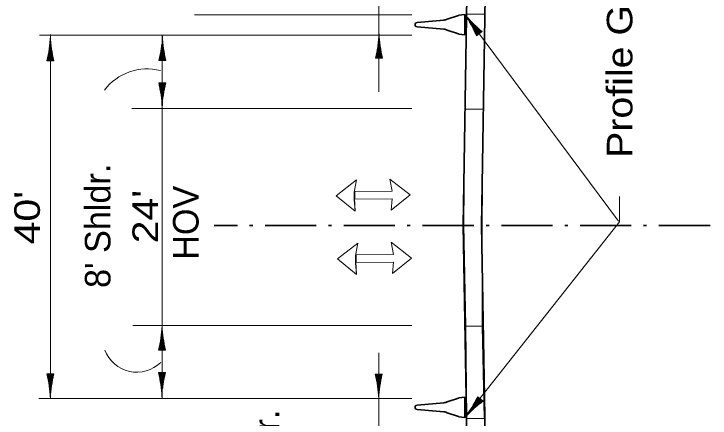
# Model space of a CAD drawing. Extents: x 2363427 to 2368559, y 6957299 to 6980140.
# Drawn here: x 2364817.6 to 2365198.6, y 6961278.3 to 6961499.8 of the extents above; entities that cross this region are included whole.
import ezdxf
from ezdxf.enums import TextEntityAlignment as Align

# ---------------------------------------------------------------- set-up
doc = ezdxf.new("R2010")
doc.units = 0
doc.header["$LTSCALE"] = 5.6
doc.linetypes.add('DOT_DASHED', pattern=[7.7, 5, -1.2, 0.3, -1.2])
for name, color, linetype, lineweight in [('3', 7, 'Continuous', 35), ('4', 7, 'Continuous', 13), ('40', 7, 'Continuous', 35), ('48', 7, 'Continuous', 25), ('8', 7, 'Continuous', 13)]:
    doc.layers.add(name, color=color, linetype=linetype, lineweight=lineweight)

msp = doc.modelspace()

# ---------------------------------------------------------------- linework, layer by layer
at = {"layer": '3'}
for p, q in [((2365063.563, 6961383.778), (2365066.183, 6961549.306)), ((2365073.563, 6961383.579), (2365076.183, 6961549.226)), ((2365054.789, 6961496.913), (2365060.903, 6961498.954)), ((2365061.067, 6961499.02), (2365061.077, 6961499.044)), ((2365064.339, 6961499.532), (2365061.077, 6961499.044)), ((2365064.339, 6961499.532), (2365061.273, 6961499.074)), ((2365064.339, 6961499.532), (2365064.339, 6961493.908)), ((2365037.269, 6961494.308), (2365037.269, 6961493.908)), ((2365053.001, 6961496.384), (2365038.297, 6961495.149)), ((2365037.269, 6961493.507), (2365037.269, 6961493.908)), ((2365053.001, 6961491.431), (2365038.297, 6961492.666)), ((2365054.789, 6961490.902), (2365060.903, 6961488.86)), ((2365064.339, 6961488.282), (2365064.339, 6961493.908)), ((2365061.067, 6961488.796), (2365061.077, 6961488.77)), ((2365064.339, 6961488.282), (2365061.077, 6961488.77)), ((2365064.339, 6961488.282), (2365061.273, 6961488.742)), ((2365063.563, 6961383.778), (2365066.169, 6961228.534)), ((2365073.563, 6961383.978), (2365076.177, 6961228.293)), ((2365054.789, 6961287.255), (2365060.903, 6961289.296)), ((2365061.067, 6961289.362), (2365061.077, 6961289.386)), ((2365064.339, 6961289.874), (2365061.077, 6961289.386)), ((2365064.339, 6961289.874), (2365061.273, 6961289.416)), ((2365064.339, 6961289.874), (2365064.339, 6961284.25)), ((2365053.001, 6961286.726), (2365038.297, 6961285.491)), ((2365037.269, 6961284.65), (2365037.269, 6961284.25)), ((2365037.269, 6961283.849), (2365037.269, 6961284.25)), ((2365053.001, 6961281.773), (2365038.297, 6961283.008)), ((2365054.789, 6961281.244), (2365060.903, 6961279.202)), ((2365064.339, 6961278.624), (2365064.339, 6961284.25)), ((2365061.067, 6961279.138), (2365061.077, 6961279.112)), ((2365064.339, 6961278.624), (2365061.077, 6961279.112)), ((2365064.339, 6961278.624), (2365061.273, 6961279.084))]:
    msp.add_line(p, q, dxfattribs=at)
at = {"layer": '3', "lineweight": 13}
for p, q in [((2365003.919, 6961397.784), (2365003.881, 6961401.879)), ((2365004.627, 6961363.108), (2365004.59, 6961367.202))]:
    msp.add_line(p, q, dxfattribs=at)
at = {"layer": '3', "linetype": 'DOT_DASHED'}
msp.add_line((2365198.639, 6961383.778), (2364927.223, 6961383.778), dxfattribs=at)
at = {"layer": '3', "lineweight": 13}
for points in [[(2365064.403, 6961447.572), (2365074.365, 6961447.572), (2365075.342, 6961499.674), (2365065.317, 6961499.575)], [(2365064.928, 6961328.633), (2365073.84, 6961328.633), (2365073.84, 6961384.173), (2365074.365, 6961447.572), (2365064.403, 6961447.572), (2365063.879, 6961384.173)], [(2365004.386, 6961391.664), (2364993.999, 6961400.199), (2365005.099, 6961408.802), (2365003.891, 6961402.074)], [(2365005.095, 6961356.988), (2364994.707, 6961365.522), (2365005.807, 6961374.125), (2365004.599, 6961367.398)], [(2365065.476, 6961278.05), (2365075.005, 6961278.05), (2365073.84, 6961328.633), (2365064.928, 6961328.633)]]:
    msp.add_lwpolyline(points, close=True, dxfattribs=at)
for points in [[(2365003.891, 6961402.074), (2365005.099, 6961408.802), (2364993.999, 6961400.199), (2365004.386, 6961391.664), (2364993.999, 6961400.199)], [(2364993.999, 6961400.199), (2365004.386, 6961391.664), (2365003.853, 6961397.979)], [(2365004.599, 6961367.398), (2365005.807, 6961374.125), (2364994.707, 6961365.522), (2365005.095, 6961356.988), (2364994.707, 6961365.522)], [(2364994.707, 6961365.522), (2365005.095, 6961356.988), (2365004.562, 6961363.302)]]:
    msp.add_lwpolyline(points, dxfattribs=at)
at = {"layer": '3'}
for centre, radius, start, end in [((2365061.451, 6961497.888), 1.2, 98.51269, 117.22516), ((2365038.416, 6961493.956), 1.2, 95.72178, 162.90786), ((2365052.5, 6961501.36), 5, 275.73538, 297.22872), ((2365038.416, 6961493.861), 1.2, 197.09214, 264.27822), ((2365052.5, 6961486.457), 5, 62.77128, 84.26462), ((2365061.451, 6961489.929), 1.2, 242.77484, 261.48731), ((2365061.451, 6961288.23), 1.2, 98.51269, 117.22516), ((2365038.417, 6961284.298), 1.2, 95.72178, 162.90786), ((2365052.501, 6961291.702), 5, 275.73538, 297.22872), ((2365038.417, 6961284.203), 1.2, 197.09214, 264.27822), ((2365052.501, 6961276.798), 5, 62.77128, 84.26462), ((2365061.451, 6961280.271), 1.2, 242.77484, 261.48731)]:
    msp.add_arc(centre, radius, start, end, dxfattribs=at)
at = {"layer": '4'}
for p, q in [((2365017.359, 6961457.18), (2365017.359, 6961524.971)), ((2365035.451, 6961499.296), (2364916.361, 6961499.296)), ((2365148.454, 6961386.156), (2365064.339, 6961499.532)), ((2365072.307, 6961488.867), (2365064.738, 6961498.896)), ((2365071.907, 6961488.568), (2365067.479, 6961494.433)), ((2365072.705, 6961489.169), (2365067.519, 6961496.04)), ((2365071.508, 6961488.265), (2365068.932, 6961491.679)), ((2365073.105, 6961489.47), (2365070.176, 6961493.351)), ((2365073.504, 6961489.771), (2365072.07, 6961491.674)), ((2364837.569, 6961383.778), (2364837.569, 6961488.46)), ((2364837.635, 6961474.097), (2364837.635, 6961486.661)), ((2364898.815, 6961289.104), (2364898.815, 6961488.046)), ((2364898.975, 6961474.263), (2364898.975, 6961486.827)), ((2365017.517, 6961475.606), (2365017.517, 6961488.17)), ((2365071.11, 6961487.965), (2365070.154, 6961489.227)), ((2365070.829, 6961487.755), (2365073.886, 6961490.06)), ((2364898.475, 6961474.263), (2364898.475, 6961482.872)), ((2365017.017, 6961475.606), (2365017.017, 6961484.216)), ((2365018.017, 6961475.606), (2365018.017, 6961482.956)), ((2364837.135, 6961474.097), (2364837.135, 6961482.706)), ((2364837.659, 6961479.332), (2364837.659, 6961480.618)), ((2364838.135, 6961474.097), (2364838.135, 6961481.447)), ((2364897.975, 6961474.263), (2364897.975, 6961479.125)), ((2364899.475, 6961474.263), (2364899.475, 6961481.613)), ((2365016.517, 6961475.606), (2365016.517, 6961480.468)), ((2365018.517, 6961475.606), (2365018.517, 6961479.883)), ((2364836.135, 6961474.097), (2364836.135, 6961476.478)), ((2364836.635, 6961474.097), (2364836.635, 6961478.959)), ((2364838.635, 6961474.097), (2364838.635, 6961478.374)), ((2364839.135, 6961474.097), (2364839.135, 6961475.682)), ((2364897.475, 6961474.263), (2364897.475, 6961476.644)), ((2364899.975, 6961474.263), (2364899.975, 6961478.54)), ((2364900.475, 6961474.263), (2364900.475, 6961475.848)), ((2365019.367, 6961475.606), (2365015.537, 6961475.606)), ((2365016.017, 6961475.606), (2365016.017, 6961477.988)), ((2365019.017, 6961475.606), (2365019.017, 6961477.192)), ((2364839.485, 6961474.097), (2364835.655, 6961474.097)), ((2364900.825, 6961474.263), (2364896.995, 6961474.263)), ((2364896.847, 6961462.03), (2364900.677, 6961462.03)), ((2364897.197, 6961462.03), (2364897.197, 6961460.445)), ((2364897.697, 6961462.03), (2364897.697, 6961457.754)), ((2364898.197, 6961462.03), (2364898.197, 6961454.68)), ((2364898.697, 6961462.03), (2364898.697, 6961449.466)), ((2364899.197, 6961462.03), (2364899.197, 6961453.42)), ((2364899.697, 6961462.03), (2364899.697, 6961457.168)), ((2364900.197, 6961462.03), (2364900.197, 6961459.648)), ((2365035.451, 6961448.046), (2364882.173, 6961448.046)), ((2365149.127, 6961399.804), (2365149.127, 6961385.89)), ((2364837.569, 6961289.878), (2364837.569, 6961383.778)), ((2365149.127, 6961385.89), (2365064.339, 6961278.624)), ((2365035.451, 6961329.104), (2364882.619, 6961329.104)), ((2364898.759, 6961315.496), (2364898.759, 6961328.06)), ((2364898.259, 6961315.496), (2364898.259, 6961324.106)), ((2364899.259, 6961315.496), (2364899.259, 6961322.846)), ((2364897.759, 6961315.496), (2364897.759, 6961320.358)), ((2364899.759, 6961315.496), (2364899.759, 6961319.773)), ((2364900.609, 6961315.496), (2364896.779, 6961315.496)), ((2364897.259, 6961315.496), (2364897.259, 6961317.878)), ((2364900.259, 6961315.496), (2364900.259, 6961317.082)), ((2365017.359, 6961246.228), (2365017.359, 6961314.02)), ((2364835.655, 6961302.592), (2364839.485, 6961302.592)), ((2364836.005, 6961302.592), (2364836.005, 6961301.006)), ((2364836.505, 6961302.592), (2364836.505, 6961298.315)), ((2364837.005, 6961302.592), (2364837.005, 6961295.242)), ((2364837.505, 6961302.592), (2364837.505, 6961290.028)), ((2364838.005, 6961302.592), (2364838.005, 6961293.982)), ((2364838.505, 6961302.592), (2364838.505, 6961297.73)), ((2364839.005, 6961302.592), (2364839.005, 6961300.21)), ((2364896.677, 6961303.37), (2364900.507, 6961303.37)), ((2364897.027, 6961303.37), (2364897.027, 6961301.785)), ((2364897.527, 6961303.37), (2364897.527, 6961299.094)), ((2364898.027, 6961303.37), (2364898.027, 6961296.02)), ((2364898.527, 6961303.37), (2364898.527, 6961290.806)), ((2364899.027, 6961303.37), (2364899.027, 6961294.76)), ((2364899.527, 6961303.37), (2364899.527, 6961298.508)), ((2364900.027, 6961303.37), (2364900.027, 6961300.988)), ((2365015.391, 6961302.46), (2365019.221, 6961302.46)), ((2365015.741, 6961302.46), (2365015.741, 6961300.875)), ((2365016.241, 6961302.46), (2365016.241, 6961298.184)), ((2365016.741, 6961302.46), (2365016.741, 6961295.11)), ((2365017.241, 6961302.46), (2365017.241, 6961289.896)), ((2365017.741, 6961302.46), (2365017.741, 6961293.85)), ((2365018.241, 6961302.46), (2365018.241, 6961297.598)), ((2365018.741, 6961302.46), (2365018.741, 6961300.078)), ((2365035.451, 6961289.104), (2364831.203, 6961289.104)), ((2365072.962, 6961288.766), (2365064.871, 6961279.154)), ((2365072.579, 6961289.088), (2365067.035, 6961282.501)), ((2365072.197, 6961289.41), (2365069.065, 6961285.69)), ((2365071.814, 6961289.732), (2365070.28, 6961287.91)), ((2365074.377, 6961287.573), (2365071.447, 6961290.041)), ((2365073.344, 6961288.443), (2365068.612, 6961282.821)), ((2365073.727, 6961288.121), (2365070.973, 6961284.85)), ((2365074.109, 6961287.799), (2365073.089, 6961286.587))]:
    msp.add_line(p, q, dxfattribs=at)
msp.add_lwpolyline([(2365035.451, 6961488.046), (2364837.907, 6961488.046), (2364831.639, 6961488.046)], dxfattribs=at)
for centre, radius, start, end in [((2365119.748, 6961545.841), 72.212, 219.88726, 230.57331), ((2365004.614, 6961458.943), 72.212, 23.5141, 34.20015), ((2364765.446, 6961490.992), 72.212, 346.47039, 357.15644), ((2364909.693, 6961490.992), 72.212, 182.84356, 193.52961), ((2364826.786, 6961491.158), 72.212, 346.47039, 357.15644), ((2364971.033, 6961491.158), 72.212, 182.84356, 193.52961), ((2364945.329, 6961492.502), 72.212, 346.47039, 357.15644), ((2365089.576, 6961492.502), 72.212, 182.84356, 193.52961), ((2364890.667, 6961440.009), 29.635, 76.01949, 142.68378), ((2364826.639, 6961445.137), 72.212, 2.84356, 13.52961), ((2364970.886, 6961445.137), 72.212, 166.47039, 177.15644), ((2364826.57, 6961332.391), 72.212, 346.47039, 357.15644), ((2364970.817, 6961332.391), 72.212, 182.84356, 193.52961), ((2364884.927, 6961322.314), 18.823, 200.84978, 313.98653), ((2364765.446, 6961285.698), 72.212, 2.84356, 13.52961), ((2364909.693, 6961285.698), 72.212, 166.47039, 177.15644), ((2364826.469, 6961286.477), 72.212, 2.84356, 13.52961), ((2364970.716, 6961286.477), 72.212, 166.47039, 177.15644), ((2364945.182, 6961285.567), 72.212, 2.84356, 13.52961), ((2365089.429, 6961285.567), 72.212, 166.47039, 177.15644), ((2365006.858, 6961322.335), 72.212, 322.74962, 333.43567), ((2365117.206, 6961229.433), 72.212, 126.37646, 137.06251)]:
    msp.add_arc(centre, radius, start, end, dxfattribs=at)
at = {"layer": '40', "lineweight": 13}
for p, q in [((2365024.644, 6961402.589), (2365004.139, 6961402.394)), ((2365024.681, 6961398.494), (2365004.177, 6961398.299)), ((2365025.353, 6961367.912), (2365004.847, 6961367.718)), ((2365025.39, 6961363.818), (2365004.885, 6961363.622))]:
    msp.add_line(p, q, dxfattribs=at)
for points in [[(2365024.681, 6961398.494), (2365024.149, 6961392.179), (2365034.537, 6961400.714), (2365023.437, 6961409.316), (2365024.644, 6961402.589)], [(2365025.39, 6961363.818), (2365024.857, 6961357.502), (2365035.245, 6961366.038), (2365024.145, 6961374.64), (2365025.353, 6961367.912)]]:
    msp.add_lwpolyline(points, dxfattribs=at)
at = {"layer": '48', "lineweight": 13}
msp.add_lwpolyline([(2365065.317, 6961499.575), (2365075.342, 6961499.674), (2365081.31, 6961776.586), (2365071.87, 6961776.586)], close=True, dxfattribs=at)
at = {"layer": '8'}
for points in [[(2365034.537, 6961400.714), (2365024.149, 6961392.179), (2365024.681, 6961398.494), (2365004.177, 6961398.299), (2365004.139, 6961402.394), (2365024.644, 6961402.589), (2365023.437, 6961409.316)], [(2365035.245, 6961366.038), (2365024.857, 6961357.502), (2365025.39, 6961363.818), (2365004.885, 6961363.622), (2365004.847, 6961367.718), (2365025.353, 6961367.912), (2365024.145, 6961374.64)]]:
    msp.add_lwpolyline(points, close=True, dxfattribs=at)

# ---------------------------------------------------------------- texts
at = {"layer": '4'}
for s, width, p in [('Profile Grade IH820', 1.15, (2365156.125, 6961516.038)), ("40'", 1.2, (2364831.821, 6961388.133)), ("24'", 1.2, (2364896.491, 6961388.723))]:
    msp.add_text(s, height=14, rotation=90, dxfattribs=dict(at, width=width)).set_placement(p, align=Align.CENTER)
for s, p in [("8' Shldr.", (2364870.449, 6961383.676)), ('HOV', (2364918.677, 6961385.358)), ('Shldr.', (2364962.897, 6961258.533))]:
    msp.add_text(s, height=14, rotation=90, dxfattribs=at).set_placement(p, align=Align.CENTER)

doc.saveas('drawing.dxf')
